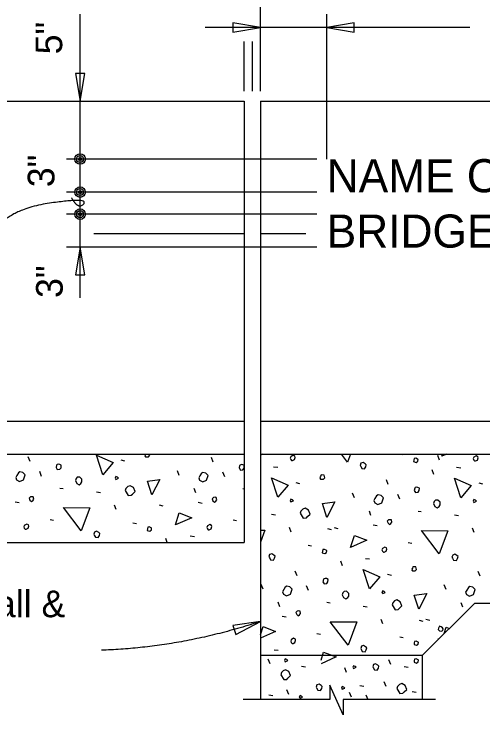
# Model space of a CAD drawing. Extents: x 130583.6 to 130653, y 88618.2 to 88652.9.
# Drawn here: x 130601.81 to 130605.35, y 88633.31 to 88638.6 of the extents above; entities that cross this region are included whole.
import ezdxf

# ---------------------------------------------------------------- set-up
doc = ezdxf.new("R2010")
doc.units = 0
for name, color, linetype in [('Dimension', 7, 'Continuous'), ('Miscellaneous', 7, 'Continuous'), ('TextStructures', 7, 'Continuous'), ('TrafBarrierConc', 7, 'Continuous')]:
    doc.layers.add(name, color=color, linetype=linetype)

msp = doc.modelspace()

# ---------------------------------------------------------------- linework, layer by layer
at = {"layer": 'Dimension'}
for p, q in [((130603.6745, 88638.019), (130603.6745, 88639.3775)), ((130602.3111, 88636.4572), (130602.3111, 88638.6002)), ((130604.1745, 88637.5059), (130604.1745, 88638.6002)), ((130605.2545, 88638.5002), (130603.2568, 88638.5002)), ((130603.552, 88638.019), (130603.552, 88638.3949)), ((130604.0995, 88637.5059), (130602.2103, 88637.5059)), ((130604.0995, 88637.2559), (130602.2103, 88637.2559)), ((130604.0995, 88637.0893), (130602.2103, 88637.0893)), ((130604.0995, 88636.8393), (130602.2103, 88636.8393))]:
    msp.add_line(p, q, dxfattribs=at)
for points in [[(130603.6745, 88638.5002), (130603.4662, 88638.5355), (130603.4662, 88638.4649)], [(130604.1745, 88638.5002), (130604.3827, 88638.4649), (130604.3827, 88638.5355)], [(130602.3111, 88637.9434), (130602.3464, 88638.1517), (130602.2759, 88638.1517)], [(130602.3111, 88636.8393), (130602.2759, 88636.631), (130602.3464, 88636.631)], [(130603.6745, 88634.0128), (130603.4657, 88633.9809), (130603.4878, 88633.9139)]]:
    msp.add_lwpolyline(points, close=True, dxfattribs=at)
msp.add_lwpolyline([(130604.9953, 88633.4221), (130604.2983, 88633.4221), (130604.2983, 88633.3058), (130604.1989, 88633.5308), (130604.1989, 88633.4221), (130603.5437, 88633.4221)], dxfattribs=at)
for centre, radius in [((130602.3119, 88637.5063), 0.0399), ((130602.3119, 88637.5063), 0.0262), ((130602.3119, 88637.5063), 0.0118), ((130602.3119, 88637.2563), 0.0399), ((130602.3119, 88637.2563), 0.0262), ((130602.3119, 88637.2563), 0.0118), ((130602.3119, 88637.0897), 0.0399), ((130602.3119, 88637.0897), 0.0262), ((130602.3119, 88637.0897), 0.0118)]:
    msp.add_circle(centre, radius, dxfattribs=at)
for points in [[(130602.2469, 88637.2126), (130602.2982, 88637.1207), (130602.3815, 88637.2173), (130601.7546, 88637.1235), (130601.629, 88636.9247)], [(130603.6745, 88634.0128), (130603.0734, 88633.814), (130602.4723, 88633.7952)]]:
    msp.add_open_spline(points, degree=2, dxfattribs=at)
at = {"layer": 'Miscellaneous'}
for p, q in [((130603.6132, 88638.019), (130603.6132, 88638.3949)), ((130601.9348, 88635.2202), (130601.9206, 88635.2556)), ((130602.6189, 88635.2326), (130602.6472, 88635.2256)), ((130603.3172, 88635.2167), (130603.303, 88635.2521)), ((130604.7295, 88635.2768), (130604.749, 88635.2729)), ((130605.0266, 88635.2322), (130605.0142, 88635.2658)), ((130603.7732, 88635.1809), (130603.8051, 88635.1774)), ((130605.1556, 88635.1774), (130605.1874, 88635.1739)), ((130602.0214, 88635.1088), (130602.0072, 88635.1442)), ((130603.0608, 88635.1159), (130603.0467, 88635.1513)), ((130603.4038, 88635.1053), (130603.3896, 88635.1407)), ((130604.9842, 88635.1226), (130604.97, 88635.158)), ((130604.6394, 88635.0466), (130604.6253, 88635.0819)), ((130602.1593, 88635.0205), (130602.184, 88635.017)), ((130603.9412, 88635.0625), (130603.9695, 88635.0554)), ((130605.3236, 88635.059), (130605.3519, 88635.0519)), ((130602.4351, 88634.9922), (130602.4651, 88634.9869)), ((130603.1864, 88634.9834), (130603.174, 88635.017)), ((130603.5417, 88635.017), (130603.552, 88635.0155)), ((130604.3831, 88634.9458), (130604.369, 88634.9812)), ((130604.7261, 88634.9352), (130604.7119, 88634.9706)), ((130601.8216, 88634.9162), (130601.8517, 88634.9109)), ((130603.204, 88634.9126), (130603.2341, 88634.9073)), ((130602.5835, 88634.8578), (130602.5711, 88634.8914)), ((130602.9088, 88634.8932), (130602.9371, 88634.8861)), ((130603.7573, 88634.8221), (130603.7874, 88634.8168)), ((130604.5086, 88634.8132), (130604.4963, 88634.8468)), ((130604.8639, 88634.8468), (130604.8887, 88634.8433)), ((130605.1397, 88634.8185), (130605.1698, 88634.8132)), ((130602.0851, 88634.7836), (130602.1116, 88634.7783)), ((130602.7108, 88634.7588), (130602.7373, 88634.7535)), ((130603.4674, 88634.78), (130603.494, 88634.7748)), ((130603.9058, 88634.6877), (130603.8934, 88634.7213)), ((130604.1798, 88634.7142), (130604.2081, 88634.7072)), ((130604.2311, 88634.7231), (130604.2594, 88634.716)), ((130604.5263, 88634.7425), (130604.5564, 88634.7372)), ((130605.2882, 88634.6842), (130605.2758, 88634.7178)), ((130603.1439, 88634.6581), (130603.1757, 88634.6546)), ((130602.9697, 88634.6101), (130602.9583, 88634.6386)), ((130604.7897, 88634.6099), (130604.8162, 88634.6046)), ((130604.0331, 88634.5887), (130604.0596, 88634.5834)), ((130604.2947, 88634.4332), (130604.2806, 88634.4685)), ((130604.4662, 88634.488), (130604.498, 88634.4844)), ((130603.95, 88634.3572), (130603.9359, 88634.3925)), ((130605.3324, 88634.3536), (130605.3183, 88634.389)), ((130604.6341, 88634.3695), (130604.6624, 88634.3625)), ((130603.6937, 88634.2564), (130603.6795, 88634.2917)), ((130604.0366, 88634.2458), (130604.0225, 88634.2811)), ((130605.0761, 88634.2529), (130605.0619, 88634.2882)), ((130603.8192, 88634.1238), (130603.8068, 88634.1574)), ((130604.1745, 88634.1574), (130604.1993, 88634.1539)), ((130604.4503, 88634.1291), (130604.4803, 88634.1238)), ((130605.2016, 88634.1203), (130605.1892, 88634.1539)), ((130603.8369, 88634.0531), (130603.8669, 88634.0478)), ((130604.5988, 88633.9948), (130604.5864, 88634.0283)), ((130604.8728, 88634.0213), (130604.9011, 88634.0142)), ((130604.9241, 88634.0301), (130604.9523, 88634.023)), ((130604.1003, 88633.9205), (130604.1268, 88633.9152)), ((130604.7261, 88633.8958), (130604.7526, 88633.8905)), ((130605.0193, 88633.8792), (130605.0177, 88633.8834)), ((130603.7768, 88633.7985), (130603.8086, 88633.795)), ((130603.7469, 88633.6918), (130603.7328, 88633.7272)), ((130604.6574, 88633.6864), (130604.6432, 88633.7217)), ((130603.9831, 88633.675), (130604.0131, 88633.6697)), ((130604.3246, 88633.6279), (130604.3105, 88633.6632)), ((130604.7601, 88633.6732), (130604.7901, 88633.6679)), ((130604.6226, 88633.5218), (130604.6085, 88633.5572)), ((130603.8877, 88633.4615), (130603.8735, 88633.4968)), ((130604.4237, 88633.5288), (130604.4537, 88633.5235)), ((130604.8204, 88633.4831), (130604.8505, 88633.4778)), ((130603.7363, 88633.4575), (130603.7663, 88633.4522)), ((130604.3612, 88633.4414), (130604.347, 88633.4767)), ((130604.4873, 88633.4194), (130604.4732, 88633.4548))]:
    msp.add_line(p, q, dxfattribs=at)
for points in [[(130602.4828, 88635.1212), (130602.4351, 88635.268), (130602.5606, 88635.2132), (130602.4828, 88635.1212)], [(130602.8052, 88635.2768), (130602.801, 88635.2697), (130602.8063, 88635.2574), (130602.8028, 88635.2609)], [(130602.8063, 88635.2574), (130602.8275, 88635.2574), (130602.8381, 88635.268), (130602.8357, 88635.2768)], [(130603.6902, 88635.2768), (130603.6745, 88635.2697)], [(130603.9094, 88635.2287), (130603.9164, 88635.2287), (130603.9306, 88635.2357), (130603.9359, 88635.2516), (130603.9341, 88635.2605), (130603.92, 88635.2676), (130603.9023, 88635.2569), (130603.8987, 88635.2463), (130603.9023, 88635.2357), (130603.9094, 88635.2287)], [(130604.3319, 88635.2163), (130604.2859, 88635.2768)], [(130604.3544, 88635.2768), (130604.3319, 88635.2163)], [(130604.8304, 88635.2198), (130604.8498, 88635.2145), (130604.8622, 88635.2234), (130604.8639, 88635.2357), (130604.8604, 88635.2393), (130604.8463, 88635.2463), (130604.8339, 88635.2446), (130604.8321, 88635.2322), (130604.8304, 88635.2198)], [(130605.0443, 88635.2605), (130605.0493, 88635.2768)], [(130605.0805, 88635.2768), (130605.0443, 88635.2605)], [(130605.2917, 88635.2251), (130605.2988, 88635.2251), (130605.313, 88635.2322), (130605.3183, 88635.2481), (130605.3165, 88635.2569), (130605.3024, 88635.264), (130605.2847, 88635.2534), (130605.2811, 88635.2428), (130605.2847, 88635.2322), (130605.2917, 88635.2251)], [(130602.131, 88635.176), (130602.1398, 88635.1601), (130602.1593, 88635.1619), (130602.1681, 88635.1743), (130602.1699, 88635.1937), (130602.1575, 88635.199), (130602.1486, 88635.2008), (130602.1381, 88635.1973), (130602.1345, 88635.1937), (130602.131, 88635.176)], [(130603.552, 88635.1903), (130603.5399, 88635.1955), (130603.531, 88635.1973), (130603.5205, 88635.1937), (130603.5169, 88635.1902), (130603.5134, 88635.1725)], [(130603.5134, 88635.1725), (130603.5222, 88635.1566), (130603.5417, 88635.1584), (130603.5505, 88635.1707), (130603.552, 88635.1868)], [(130604.4308, 88635.1845), (130604.4397, 88635.1686), (130604.4609, 88635.165), (130604.4697, 88635.1809), (130604.4733, 88635.1951), (130604.4644, 88635.2039), (130604.4485, 88635.2128), (130604.4326, 88635.2074), (130604.4273, 88635.1915), (130604.4308, 88635.1845)], [(130601.8322, 88635.0823), (130601.8552, 88635.07), (130601.8853, 88635.0823), (130601.8977, 88635.1195), (130601.8799, 88635.1372), (130601.857, 88635.1424), (130601.8464, 88635.1354), (130601.834, 88635.1159), (130601.8252, 88635.1), (130601.8322, 88635.0823)], [(130603.2146, 88635.0788), (130603.2376, 88635.0664), (130603.2677, 88635.0788), (130603.2801, 88635.1159), (130603.2623, 88635.1336), (130603.2394, 88635.1389), (130603.2288, 88635.1319), (130603.2164, 88635.1124), (130603.2076, 88635.0965), (130603.2146, 88635.0788)], [(130602.2759, 88635.0771), (130602.2866, 88635.0558), (130602.3042, 88635.0452), (130602.3184, 88635.0558), (130602.3255, 88635.0664), (130602.3255, 88635.0876), (130602.3095, 88635.1036), (130602.2901, 88635.1018), (130602.2812, 88635.093), (130602.2759, 88635.0771)], [(130602.5818, 88635.0859), (130602.6012, 88635.0947), (130602.5942, 88635.1018), (130602.5818, 88635.1071), (130602.5765, 88635.0947), (130602.5818, 88635.0859)], [(130602.854, 88634.9692), (130602.8204, 88635.0735), (130602.9141, 88635.0859), (130602.854, 88634.9692)], [(130603.8051, 88634.9511), (130603.7573, 88635.0978), (130603.8828, 88635.043), (130603.8051, 88634.9511)], [(130604.1286, 88635.0872), (130604.1498, 88635.0872), (130604.1604, 88635.0978), (130604.1551, 88635.1173), (130604.1321, 88635.1191), (130604.1286, 88635.1085), (130604.1233, 88635.0996), (130604.1286, 88635.0872), (130604.125, 88635.0908)], [(130605.1874, 88634.9476), (130605.1397, 88635.0943), (130605.2652, 88635.0395), (130605.1874, 88634.9476)], [(130602.6525, 88635.001), (130602.6755, 88634.9639), (130602.6984, 88634.9657), (130602.7073, 88634.9745), (130602.7267, 88634.9939), (130602.7144, 88635.024), (130602.6896, 88635.0382), (130602.6719, 88635.0311), (130602.6578, 88635.017), (130602.6525, 88635.001)], [(130604.8357, 88635.0024), (130604.8445, 88634.9865), (130604.8639, 88634.9882), (130604.8728, 88635.0006), (130604.8746, 88635.0201), (130604.8622, 88635.0254), (130604.8533, 88635.0271), (130604.8427, 88635.0236), (130604.8392, 88635.0201), (130604.8357, 88635.0024)], [(130604.5369, 88634.9087), (130604.5599, 88634.8963), (130604.5899, 88634.9087), (130604.6023, 88634.9458), (130604.5846, 88634.9635), (130604.5617, 88634.9688), (130604.5511, 88634.9617), (130604.5387, 88634.9423), (130604.5298, 88634.9264), (130604.5369, 88634.9087)], [(130601.933, 88634.9285), (130601.9436, 88634.918), (130601.9542, 88634.925), (130601.9613, 88634.9356), (130601.9578, 88634.9533), (130601.9489, 88634.9551), (130601.9366, 88634.9533), (130601.9259, 88634.9427), (130601.933, 88634.9285)], [(130603.3154, 88634.925), (130603.326, 88634.9144), (130603.3366, 88634.9215), (130603.3437, 88634.9321), (130603.3402, 88634.9498), (130603.3313, 88634.9515), (130603.319, 88634.9498), (130603.3083, 88634.9392), (130603.3154, 88634.925)], [(130603.9041, 88634.9158), (130603.9235, 88634.9246), (130603.9164, 88634.9317), (130603.9041, 88634.937), (130603.8987, 88634.9246), (130603.9041, 88634.9158)], [(130604.1763, 88634.7991), (130604.1427, 88634.9034), (130604.2364, 88634.9158), (130604.1763, 88634.7991)], [(130604.9806, 88634.9034), (130604.9912, 88634.8822), (130605.0089, 88634.8716), (130605.023, 88634.8822), (130605.0301, 88634.8928), (130605.0301, 88634.914), (130605.0142, 88634.9299), (130604.9948, 88634.9281), (130604.9859, 88634.9193), (130604.9806, 88634.9034)], [(130605.2864, 88634.9122), (130605.3059, 88634.9211), (130605.2988, 88634.9281), (130605.2864, 88634.9334), (130605.2811, 88634.9211), (130605.2864, 88634.9122)], [(130602.3202, 88634.697), (130602.1858, 88634.8737), (130602.3856, 88634.872), (130602.3202, 88634.697)], [(130603.9748, 88634.8309), (130603.9977, 88634.7938), (130604.0207, 88634.7956), (130604.0296, 88634.8044), (130604.049, 88634.8238), (130604.0366, 88634.8539), (130604.0119, 88634.868), (130603.9942, 88634.861), (130603.9801, 88634.8468), (130603.9748, 88634.8309)], [(130603.0326, 88634.7412), (130603.0608, 88634.8331), (130603.1545, 88634.796), (130603.0326, 88634.7412)], [(130604.6377, 88634.7549), (130604.6483, 88634.7443), (130604.6589, 88634.7514), (130604.666, 88634.762), (130604.6624, 88634.7796), (130604.6536, 88634.7814), (130604.6412, 88634.7796), (130604.6306, 88634.769), (130604.6377, 88634.7549)], [(130601.8977, 88634.7094), (130601.9047, 88634.7094), (130601.9189, 88634.7164), (130601.9242, 88634.7323), (130601.9224, 88634.7412), (130601.9083, 88634.7482), (130601.8906, 88634.7376), (130601.887, 88634.727), (130601.8906, 88634.7164), (130601.8977, 88634.7094)], [(130602.8186, 88634.7005), (130602.8381, 88634.6952), (130602.8505, 88634.704), (130602.8522, 88634.7164), (130602.8487, 88634.7199), (130602.8346, 88634.727), (130602.8222, 88634.7252), (130602.8204, 88634.7129), (130602.8186, 88634.7005)], [(130603.2801, 88634.7058), (130603.2871, 88634.7058), (130603.3013, 88634.7129), (130603.3066, 88634.7288), (130603.3048, 88634.7376), (130603.2906, 88634.7447), (130603.273, 88634.7341), (130603.2694, 88634.7235), (130603.273, 88634.7129), (130603.2801, 88634.7058)], [(130603.6745, 88634.7022), (130603.7078, 88634.7019), (130603.6745, 88634.6127)], [(130605.0248, 88634.5233), (130604.8905, 88634.7001), (130605.0902, 88634.6983), (130605.0248, 88634.5233)], [(130602.4191, 88634.6651), (130602.428, 88634.6493), (130602.4492, 88634.6457), (130602.458, 88634.6616), (130602.4616, 88634.6758), (130602.4527, 88634.6846), (130602.4368, 88634.6934), (130602.4209, 88634.6881), (130602.4156, 88634.6722), (130602.4191, 88634.6651)], [(130604.3548, 88634.5711), (130604.3831, 88634.663), (130604.4768, 88634.6259), (130604.3548, 88634.5711)], [(130604.1409, 88634.5304), (130604.1604, 88634.5251), (130604.1728, 88634.5339), (130604.1745, 88634.5463), (130604.171, 88634.5498), (130604.1568, 88634.5569), (130604.1445, 88634.5551), (130604.1427, 88634.5428), (130604.1409, 88634.5304)], [(130604.6023, 88634.5357), (130604.6094, 88634.5357), (130604.6235, 88634.5428), (130604.6288, 88634.5587), (130604.6271, 88634.5675), (130604.6129, 88634.5746), (130604.5952, 88634.564), (130604.5917, 88634.5534), (130604.5952, 88634.5428), (130604.6023, 88634.5357)], [(130603.7414, 88634.495), (130603.7503, 88634.4791), (130603.7715, 88634.4756), (130603.7803, 88634.4915), (130603.7838, 88634.5056), (130603.775, 88634.5145), (130603.7591, 88634.5233), (130603.7432, 88634.518), (130603.7379, 88634.5021), (130603.7414, 88634.495)], [(130605.1238, 88634.4915), (130605.1326, 88634.4756), (130605.1539, 88634.4721), (130605.1627, 88634.488), (130605.1662, 88634.5021), (130605.1574, 88634.5109), (130605.1415, 88634.5198), (130605.1256, 88634.5145), (130605.1203, 88634.4986), (130605.1238, 88634.4915)], [(130604.498, 88634.2582), (130604.4503, 88634.4049), (130604.5758, 88634.3501), (130604.498, 88634.2582)], [(130604.8215, 88634.3943), (130604.8427, 88634.3943), (130604.8533, 88634.4049), (130604.848, 88634.4243), (130604.8251, 88634.4261), (130604.8215, 88634.4155), (130604.8162, 88634.4066), (130604.8215, 88634.3943), (130604.818, 88634.3978)], [(130604.1462, 88634.313), (130604.1551, 88634.297), (130604.1745, 88634.2988), (130604.1834, 88634.3112), (130604.1851, 88634.3306), (130604.1728, 88634.3359), (130604.1639, 88634.3377), (130604.1533, 88634.3342), (130604.1498, 88634.3306), (130604.1462, 88634.313)], [(130603.8475, 88634.2193), (130603.8705, 88634.2069), (130603.9005, 88634.2193), (130603.9129, 88634.2564), (130603.8952, 88634.2741), (130603.8722, 88634.2794), (130603.8616, 88634.2723), (130603.8493, 88634.2529), (130603.8404, 88634.2369), (130603.8475, 88634.2193)], [(130604.2912, 88634.214), (130604.3018, 88634.1927), (130604.3195, 88634.1821), (130604.3336, 88634.1927), (130604.3407, 88634.2034), (130604.3407, 88634.2246), (130604.3248, 88634.2405), (130604.3053, 88634.2387), (130604.2965, 88634.2299), (130604.2912, 88634.214)], [(130604.597, 88634.2228), (130604.6165, 88634.2316), (130604.6094, 88634.2387), (130604.597, 88634.244), (130604.5917, 88634.2316), (130604.597, 88634.2228)], [(130605.2299, 88634.2157), (130605.2529, 88634.2034), (130605.2829, 88634.2157), (130605.2953, 88634.2529), (130605.2776, 88634.2705), (130605.2546, 88634.2758), (130605.244, 88634.2688), (130605.2316, 88634.2493), (130605.2228, 88634.2334), (130605.2299, 88634.2157)], [(130604.6677, 88634.1379), (130604.6907, 88634.1008), (130604.7137, 88634.1026), (130604.7225, 88634.1114), (130604.742, 88634.1309), (130604.7296, 88634.1609), (130604.7048, 88634.1751), (130604.6872, 88634.168), (130604.673, 88634.1539), (130604.6677, 88634.1379)], [(130604.8693, 88634.1061), (130604.8357, 88634.2104), (130604.9294, 88634.2228), (130604.8693, 88634.1061)], [(130603.9482, 88634.0655), (130603.9589, 88634.0549), (130603.9695, 88634.0619), (130603.9765, 88634.0725), (130603.973, 88634.0902), (130603.9642, 88634.092), (130603.9518, 88634.0902), (130603.9412, 88634.0796), (130603.9482, 88634.0655)], [(130603.6745, 88633.9112), (130603.6937, 88633.9735), (130603.7874, 88633.9364), (130603.6745, 88633.8857)], [(130604.3354, 88633.8339), (130604.201, 88634.0107), (130604.4008, 88634.0089), (130604.3354, 88633.8339)], [(130605.0266, 88633.9417), (130605.039, 88633.94), (130605.0513, 88633.9453), (130605.0549, 88633.9559), (130605.0496, 88633.9647), (130605.039, 88633.9718), (130605.0266, 88633.9771), (130605.0195, 88633.9629), (130605.016, 88633.9523), (130605.0266, 88633.9417)], [(130605.061, 88633.9209), (130605.0761, 88633.97), (130605.1004, 88633.9604)], [(130603.9129, 88633.8463), (130603.92, 88633.8463), (130603.9341, 88633.8533), (130603.9394, 88633.8692), (130603.9376, 88633.8781), (130603.9235, 88633.8852), (130603.9058, 88633.8746), (130603.9023, 88633.8639), (130603.9058, 88633.8533), (130603.9129, 88633.8463)], [(130604.8339, 88633.8374), (130604.8533, 88633.8321), (130604.8657, 88633.841), (130604.8675, 88633.8533), (130604.8639, 88633.8569), (130604.8498, 88633.8639), (130604.8374, 88633.8622), (130604.8357, 88633.8498), (130604.8339, 88633.8374)], [(130604.4344, 88633.8021), (130604.4432, 88633.7862), (130604.4644, 88633.7826), (130604.4733, 88633.7985), (130604.4768, 88633.8127), (130604.468, 88633.8215), (130604.4521, 88633.8304), (130604.4361, 88633.8251), (130604.4308, 88633.8091), (130604.4344, 88633.8021)], [(130604.1321, 88633.7187), (130604.1513, 88633.781), (130604.245, 88633.7439), (130604.1321, 88633.6932)], [(130603.8611, 88633.7082), (130603.8806, 88633.717), (130603.8735, 88633.7241), (130603.8611, 88633.7294), (130603.8558, 88633.717), (130603.8611, 88633.7082)], [(130604.8339, 88633.7038), (130604.8533, 88633.6984), (130604.8657, 88633.7073), (130604.8675, 88633.7197), (130604.8639, 88633.7232), (130604.8498, 88633.7303), (130604.8374, 88633.7285), (130604.8357, 88633.7161), (130604.8339, 88633.7038)], [(130603.8267, 88633.6102), (130603.8497, 88633.5731), (130603.8727, 88633.5748), (130603.8815, 88633.5837), (130603.901, 88633.6031), (130603.8886, 88633.6332), (130603.8639, 88633.6473), (130603.8462, 88633.6403), (130603.8321, 88633.6261), (130603.8267, 88633.6102)], [(130604.3767, 88633.657), (130604.3961, 88633.6659), (130604.3891, 88633.6729), (130604.3767, 88633.6782), (130604.3714, 88633.6659), (130604.3767, 88633.657)], [(130604.5262, 88633.6636), (130604.5351, 88633.6477), (130604.5563, 88633.6441), (130604.5651, 88633.66), (130604.5687, 88633.6742), (130604.5598, 88633.683), (130604.5439, 88633.6919), (130604.528, 88633.6865), (130604.5227, 88633.6706), (130604.5262, 88633.6636)], [(130604.0984, 88633.51), (130604.1073, 88633.4941), (130604.1285, 88633.4906), (130604.1373, 88633.5065), (130604.1409, 88633.5206), (130604.132, 88633.5294), (130604.1161, 88633.5383), (130604.1002, 88633.533), (130604.0949, 88633.5171), (130604.0984, 88633.51)], [(130604.7043, 88633.506), (130604.7273, 88633.4689), (130604.7503, 88633.4706), (130604.7591, 88633.4795), (130604.7785, 88633.4989), (130604.7662, 88633.529), (130604.7414, 88633.5431), (130604.7237, 88633.536), (130604.7096, 88633.5219), (130604.7043, 88633.506)], [(130604.2908, 88633.4998), (130604.3102, 88633.5086), (130604.3031, 88633.5157), (130604.2908, 88633.521), (130604.2855, 88633.5086), (130604.2908, 88633.4998)], [(130603.9727, 88633.4321), (130603.9921, 88633.441), (130603.985, 88633.4481), (130603.9727, 88633.4534), (130603.9674, 88633.441), (130603.9727, 88633.4321)]]:
    msp.add_lwpolyline(points, dxfattribs=at)
at = {"layer": 'TrafBarrierConc'}
for p, q in [((130593.8226, 88637.9434), (130603.552, 88637.9434)), ((130603.552, 88637.9434), (130603.552, 88634.6101)), ((130603.6745, 88637.9434), (130607.3086, 88637.9434)), ((130603.6745, 88637.9434), (130603.6745, 88633.4221)), ((130602.4147, 88636.9434), (130603.552, 88636.9434)), ((130603.6745, 88636.9434), (130604.0154, 88636.9434)), ((130593.8226, 88635.5268), (130603.552, 88635.5268)), ((130603.6745, 88635.5268), (130607.3086, 88635.5268)), ((130593.8226, 88635.2768), (130603.552, 88635.2768)), ((130603.6745, 88635.2768), (130607.3086, 88635.2768)), ((130593.8226, 88634.6101), (130603.552, 88634.6101)), ((130604.8945, 88633.7544), (130605.2918, 88634.1518)), ((130605.2918, 88634.1518), (130607.3086, 88634.1518)), ((130604.8945, 88633.7544), (130603.6745, 88633.7544)), ((130604.8945, 88633.7544), (130604.8945, 88633.4221))]:
    msp.add_line(p, q, dxfattribs=at)

# ---------------------------------------------------------------- texts
at = {"layer": 'Dimension'}
msp.add_text('Front Face of Backwall &', height=0.2016, dxfattribs=at).set_placement((130599.204, 88634.0445))
at = {"layer": 'TextStructures'}
for s, p in [('5"', (130602.1766, 88638.2972)), ('3"', (130602.118, 88637.2933)), ('3"', (130602.1805, 88636.4567))]:
    msp.add_text(s, height=0.2016, rotation=90, dxfattribs=at).set_placement(p)
for s, p in [('NAME OR DATE', (130604.1743, 88637.2551)), ('BRIDGE NUMBER', (130604.1743, 88636.8369))]:
    msp.add_text(s, height=0.250048, dxfattribs=at).set_placement(p)

doc.saveas('drawing.dxf')
